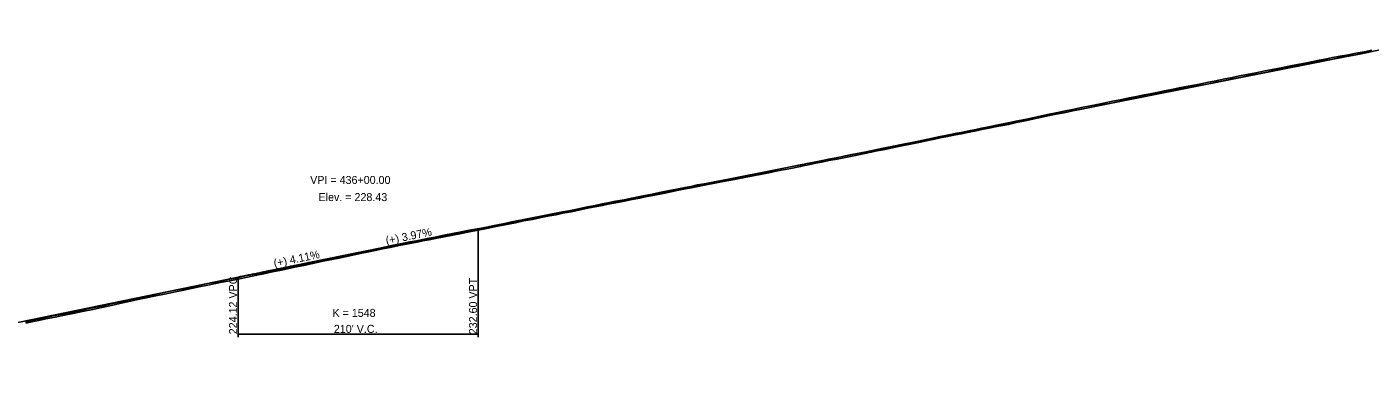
# Model space of a CAD drawing. Extents: x 1876258 to 1932803, y 754739 to 837911.
# Drawn here: x 1921673 to 1922849, y 831045 to 831344 of the extents above; entities that cross this region are included whole.
import ezdxf

# ---------------------------------------------------------------- set-up
doc = ezdxf.new("R2010")
doc.units = 0
for name, color, linetype in [('RD_DDB_GradeTX', 7, 'Continuous'), ('RD_DDB_Profile_EX', 7, 'Continuous'), ('RD_DDB_Profile_Lbl', 7, 'Continuous'), ('RD_DDB_Profile_PR', 7, 'Continuous'), ('RD_DDB_StripGrade', 7, 'Continuous'), ('RD_DDB_VCLbl', 7, 'Continuous'), ('RD_Sketch1', 7, 'Continuous')]:
    doc.layers.add(name, color=color, linetype=linetype)

msp = doc.modelspace()

# ---------------------------------------------------------------- linework, layer by layer
at = {"layer": 'RD_DDB_GradeTX'}
for p in [(1922041.5, 831162), (1921884.7, 831130.4)]:
    msp.add_line(p, (1921963.1, 831146.5), dxfattribs=at)
at = {"layer": 'RD_DDB_Profile_EX'}
for points in [[(1922539, 831260.2), (1922546.6, 831261.8), (1922553.5, 831263.3), (1922561.2, 831264.9), (1922568.1, 831266.3), (1922573.9, 831267.5), (1922580.7, 831268.9), (1922588.4, 831270.5), (1922596.2, 831272.1), (1922609.8, 831274.9), (1922615.6, 831276.1), (1922623.4, 831277.6), (1922630.1, 831279), (1922637.8, 831280.6), (1922644.3, 831281.8), (1922649.6, 831283), (1922656.3, 831284.3), (1922662.2, 831285.5), (1922668.7, 831286.8), (1922676.6, 831288.4), (1922683.1, 831289.7), (1922692.8, 831291.5), (1922699.4, 831292.8), (1922705.9, 831294), (1922713.7, 831295.6), (1922720, 831296.9), (1922728, 831298.5), (1922734.5, 831299.8), (1922742.3, 831301.4), (1922748.8, 831302.6), (1922756.7, 831304.2), (1922763.2, 831305.6), (1922770.9, 831307.1), (1922777.6, 831308.4), (1922785.3, 831310), (1922791.8, 831311.2), (1922798.9, 831312.5), (1922802.8, 831313.3), (1922810.5, 831314.8), (1922815.9, 831315.8), (1922822.4, 831317.1), (1922829.8, 831318.5), (1922836.3, 831319.7), (1922843.6, 831321.1), (1922850.2, 831322.4)], [(1921856.5, 831122.9), (1921861, 831123.8), (1921866.3, 831124.9), (1921874.3, 831126.6), (1921880.6, 831127.9), (1921888.2, 831129.5), (1921896, 831131.1), (1921901.3, 831132.2), (1921909, 831133.8), (1921916.9, 831135.5), (1921924.6, 831137.1), (1921932.4, 831138.8), (1921940.1, 831140.4), (1921947.5, 831141.9), (1921955.8, 831143.6), (1921964.9, 831145.5), (1921972.4, 831147), (1921979.3, 831148.4), (1921984.8, 831149.6), (1921992.6, 831151.2), (1922000.3, 831152.8), (1922008.6, 831154.4), (1922016.1, 831155.9), (1922019.7, 831156.6), (1922025.1, 831157.6), (1922030.6, 831158.8), (1922038.2, 831160.3), (1922045.8, 831161.8), (1922053.4, 831163.2), (1922059, 831164.4), (1922068.1, 831166.1), (1922075.7, 831167.6), (1922082.3, 831168.9), (1922091.5, 831170.7), (1922096.2, 831171.7), (1922100.6, 831172.6), (1922108.1, 831174.1), (1922115.6, 831175.5), (1922123.3, 831177.1), (1922130.4, 831178.5), (1922136.2, 831179.6), (1922142.1, 831180.8), (1922149.7, 831182.2), (1922157.2, 831183.8), (1922164, 831185.2), (1922170.5, 831186.5), (1922176.8, 831187.7), (1922181.7, 831188.7), (1922188.5, 831190), (1922196.1, 831191.5), (1922202.7, 831192.9), (1922209.6, 831194.2), (1922214.2, 831195.1), (1922219.3, 831196.2), (1922226.9, 831197.7), (1922234.2, 831199.1), (1922242.1, 831200.7), (1922249.4, 831202.2), (1922254.6, 831203.2), (1922260.2, 831204.3), (1922267.7, 831205.8), (1922275.1, 831207.2), (1922282.5, 831208.6), (1922289, 831209.8), (1922293.7, 831210.8), (1922301, 831212.2), (1922308.6, 831213.6), (1922314.7, 831214.8), (1922322.3, 831216.3), (1922330, 831217.9), (1922341.5, 831220.1), (1922350.1, 831221.9), (1922353.4, 831222.6), (1922355.9, 831223), (1922362.2, 831224.3), (1922369.9, 831225.8), (1922374.9, 831226.9), (1922382.1, 831228.3), (1922389.5, 831229.8), (1922396.7, 831231.2), (1922404.8, 831232.9), (1922412, 831234.3), (1922417.1, 831235.4), (1922424.2, 831236.8), (1922431.7, 831238.4), (1922438.9, 831239.8), (1922446.3, 831241.4), (1922453.7, 831242.9), (1922460.3, 831244.2), (1922466, 831245.4), (1922472.5, 831246.8), (1922478.8, 831248), (1922487.2, 831249.7), (1922491, 831250.5), (1922497.8, 831251.8), (1922503.8, 831253), (1922508.8, 831254.1), (1922515.2, 831255.4), (1922520.4, 831256.4), (1922532.1, 831258.7), (1922539, 831260.2)], [(1921672.2, 831084.7), (1921680.5, 831086.4), (1921683.6, 831087), (1921689.7, 831088.3), (1921698.1, 831090), (1921706.2, 831091.7), (1921713.6, 831093.1), (1921721.8, 831094.7), (1921730.9, 831096.7), (1921738.9, 831098.4), (1921745.9, 831099.8), (1921754.4, 831101.7), (1921761.3, 831103.2), (1921769.2, 831104.9), (1921777.7, 831106.7), (1921785.9, 831108.5), (1921793.6, 831110.1), (1921801.8, 831111.8), (1921810.4, 831113.6), (1921817.1, 831115), (1921823.9, 831116.4), (1921831.6, 831118), (1921838.3, 831119.3), (1921845.4, 831120.7), (1921850.8, 831121.8), (1921856.5, 831122.9)]]:
    msp.add_lwpolyline(points, dxfattribs=at)
at = {"layer": 'RD_DDB_Profile_PR'}
for p, q in [((1922068.1, 831167.3), (1922958.1, 831344.1)), ((1921470.1, 831045.2), (1921858.1, 831124.9))]:
    msp.add_line(p, q, dxfattribs=at)
msp.add_spline([(1921858.1, 831124.9), (1921862.3, 831125.8), (1921866.5, 831126.6), (1921870.7, 831127.5), (1921874.9, 831128.3), (1921879.1, 831129.2), (1921883.3, 831130.1), (1921887.5, 831130.9), (1921891.7, 831131.8), (1921895.9, 831132.6), (1921900.1, 831133.5), (1921904.3, 831134.4), (1921908.5, 831135.2), (1921912.7, 831136.1), (1921916.9, 831136.9), (1921921.1, 831137.8), (1921925.3, 831138.6), (1921929.5, 831139.5), (1921933.7, 831140.3), (1921937.9, 831141.2), (1921942.1, 831142), (1921946.3, 831142.9), (1921950.5, 831143.7), (1921954.7, 831144.6), (1921958.9, 831145.4), (1921963.1, 831146.3), (1921967.3, 831147.1), (1921971.5, 831148), (1921975.7, 831148.8), (1921979.9, 831149.7), (1921984.1, 831150.5), (1921988.3, 831151.4), (1921992.5, 831152.2), (1921996.7, 831153.1), (1922000.9, 831153.9), (1922005.1, 831154.7), (1922009.3, 831155.6), (1922013.5, 831156.4), (1922017.7, 831157.3), (1922021.9, 831158.1), (1922026.1, 831158.9), (1922030.3, 831159.8), (1922034.5, 831160.6), (1922038.7, 831161.5), (1922042.9, 831162.3), (1922047.1, 831163.1), (1922051.3, 831164), (1922055.5, 831164.8), (1922059.7, 831165.6), (1922063.9, 831166.5), (1922068.1, 831167.3)], degree=3, dxfattribs=at)
at = {"layer": 'RD_DDB_VCLbl'}
for p, q in [((1922068.1, 831072.4), (1922068.1, 831167.3)), ((1921858.1, 831072.4), (1921858.1, 831124.9)), ((1921858.1, 831074.9), (1922068.1, 831074.9))]:
    msp.add_line(p, q, dxfattribs=at)
at = {"layer": 'RD_Sketch1'}
msp.add_lwpolyline([(1921672, 831085.9), (1921680.2, 831087.6), (1921683.4, 831088.2), (1921689.4, 831089.5), (1921697.8, 831091.2), (1921706, 831092.9), (1921713.4, 831094.3), (1921721.6, 831096), (1921730.6, 831098), (1921738.7, 831099.6), (1921745.6, 831101.1), (1921754.1, 831102.9), (1921761, 831104.4), (1921768.9, 831106.1), (1921777.4, 831108), (1921785.7, 831109.7), (1921793.3, 831111.4), (1921801.5, 831113.1), (1921810.1, 831114.8), (1921816.9, 831116.2), (1921823.7, 831117.7), (1921831.3, 831119.2), (1921838.1, 831120.5), (1921845.1, 831122), (1921850.6, 831123), (1921856.3, 831124.1), (1921860.7, 831125.1), (1921866, 831126.2), (1921874, 831127.8), (1921880.3, 831129.1), (1921888, 831130.7), (1921895.7, 831132.3), (1921901.1, 831133.4), (1921908.8, 831135), (1921916.6, 831136.7), (1921924.3, 831138.4), (1921932.1, 831140), (1921939.8, 831141.6), (1921947.3, 831143.1), (1921955.6, 831144.8), (1921964.7, 831146.7), (1921972.1, 831148.2), (1921979, 831149.6), (1921984.6, 831150.8), (1921992.3, 831152.5), (1922000.1, 831154.1), (1922008.4, 831155.7), (1922015.8, 831157.1), (1922019.4, 831157.8), (1922024.8, 831158.9), (1922030.4, 831160), (1922038, 831161.6), (1922045.6, 831163), (1922053.1, 831164.5), (1922058.8, 831165.6), (1922067.8, 831167.3), (1922075.5, 831168.8), (1922082.1, 831170.2), (1922091.3, 831172), (1922096, 831172.9), (1922100.3, 831173.8), (1922107.9, 831175.3), (1922115.4, 831176.8), (1922123, 831178.3), (1922130.2, 831179.7), (1922135.9, 831180.8), (1922141.8, 831182), (1922149.4, 831183.4), (1922157, 831185), (1922163.8, 831186.4), (1922170.3, 831187.7), (1922176.5, 831189), (1922181.4, 831189.9), (1922188.3, 831191.3), (1922195.8, 831192.7), (1922202.5, 831194.1), (1922209.4, 831195.5), (1922213.9, 831196.4), (1922219, 831197.4), (1922226.6, 831198.9), (1922234, 831200.4), (1922241.9, 831201.9), (1922249.1, 831203.4), (1922254.4, 831204.4), (1922259.9, 831205.6), (1922267.5, 831207), (1922274.8, 831208.4), (1922282.3, 831209.8), (1922288.7, 831211.1), (1922293.5, 831212), (1922300.8, 831213.4), (1922308.4, 831214.8), (1922314.5, 831216), (1922322, 831217.5), (1922329.8, 831219.1), (1922341.3, 831221.4), (1922349.9, 831223.1), (1922353.2, 831223.8), (1922355.7, 831224.3), (1922362, 831225.5), (1922369.6, 831227), (1922374.6, 831228.1), (1922381.8, 831229.5), (1922389.3, 831231), (1922396.5, 831232.5), (1922404.5, 831234.1), (1922411.7, 831235.5), (1922416.8, 831236.6), (1922423.9, 831238), (1922431.4, 831239.6), (1922438.6, 831241.1), (1922446.1, 831242.6), (1922453.4, 831244.1), (1922460, 831245.4), (1922465.7, 831246.6), (1922472.3, 831248), (1922478.5, 831249.2), (1922486.9, 831251), (1922490.7, 831251.7), (1922497.5, 831253.1), (1922503.6, 831254.2), (1922508.6, 831255.3), (1922515, 831256.6), (1922520.1, 831257.6), (1922531.8, 831260), (1922538.8, 831261.5), (1922546.3, 831263), (1922553.3, 831264.5), (1922560.9, 831266.1), (1922567.8, 831267.5), (1922573.7, 831268.8), (1922580.4, 831270.1), (1922588.2, 831271.8), (1922595.9, 831273.3), (1922609.6, 831276.2), (1922615.3, 831277.3), (1922623.1, 831278.9), (1922629.9, 831280.2), (1922637.6, 831281.8), (1922644.1, 831283.1), (1922649.3, 831284.2), (1922656.1, 831285.5), (1922662, 831286.7), (1922668.5, 831288.1), (1922676.3, 831289.6), (1922682.9, 831290.9), (1922692.6, 831292.7), (1922699.1, 831294), (1922705.6, 831295.3), (1922713.4, 831296.8), (1922719.8, 831298.2), (1922727.7, 831299.7), (1922734.3, 831301.1), (1922742.1, 831302.6), (1922748.6, 831303.9), (1922756.4, 831305.5), (1922762.9, 831306.8), (1922770.7, 831308.3), (1922777.3, 831309.6), (1922785.1, 831311.2), (1922791.6, 831312.4), (1922798.6, 831313.7), (1922802.5, 831314.5), (1922810.3, 831316), (1922815.7, 831317.1), (1922822.2, 831318.4), (1922829.5, 831319.7), (1922836.1, 831321), (1922843.4, 831322.3), (1922849.9, 831323.6)], dxfattribs=at)

# ---------------------------------------------------------------- texts
at = {"layer": 'RD_DDB_GradeTX'}
for s, rotation, p in [('(+) 3.97%', 11.2327, (1921987.9, 831153.4)), ('(+) 4.11%', 11.6061, (1921889.9, 831133.5))]:
    msp.add_text(s, height=7, rotation=rotation, dxfattribs=at).set_placement(p)
at = {"layer": 'RD_DDB_Profile_Lbl'}
for s, p in [('VPI = 436+00.00', (1921921.1, 831206.5)), ('Elev. = 228.43', (1921928.4, 831191.5))]:
    msp.add_text(s, height=7, dxfattribs=at).set_placement(p)
at = {"layer": 'RD_DDB_StripGrade'}
for s, p in [('224.12 VPC', (1921857.1, 831074.9)), ('232.60 VPT', (1922067.1, 831074.9))]:
    msp.add_text(s, height=7, rotation=90, dxfattribs=at).set_placement(p)
at = {"layer": 'RD_DDB_VCLbl'}
for s, p in [('K = 1548', (1921940.6, 831090.1)), ("210' V.C.", (1921941.8, 831076.1))]:
    msp.add_text(s, height=7, dxfattribs=at).set_placement(p)

doc.saveas('drawing.dxf')
